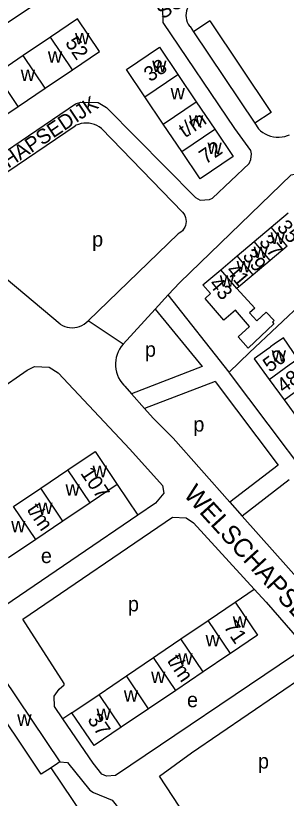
# Model space of a CAD drawing. Extents: x 157569 to 159501, y 382907 to 384670.
# Drawn here: x 157888.3 to 157961.3, y 383461.2 to 383672.3 of the extents above; entities that cross this region are included whole.
import ezdxf

# ---------------------------------------------------------------- set-up
doc = ezdxf.new("R2010")
doc.units = 0
for name, color, linetype in [('BLT_Basislijn', 7, 'Continuous'), ('BLT_Bebouwing', 7, 'Continuous'), ('BLT_Centroide', 7, 'Continuous'), ('BLT_Huisnummer', 7, 'Continuous'), ('BLT_Huisnummer_ tussenligend', 7, 'Continuous'), ('BLT_Huisnummer_reeks', 7, 'Continuous'), ('BLT_Onderverdeling_panden', 7, 'Continuous'), ('BLT_Straatnaam', 7, 'Continuous'), ('BLT_Straatnaam_verkleind', 7, 'Continuous'), ('BLT_Vlakafsluiter', 7, 'Continuous')]:
    doc.layers.add(name, color=color, linetype=linetype)

msp = doc.modelspace()

# ---------------------------------------------------------------- linework, layer by layer
at = {"layer": 'BLT_Basislijn'}
for p, q in [((157935.32, 383669.37), (157936.25, 383667.97)), ((157940.69, 383670.91), (157936.25, 383667.97)), ((157940.69, 383670.91), (157957.21, 383646.24)), ((157936.25, 383667.97), (157952.77, 383643.3)), ((157957.21, 383646.24), (157952.77, 383643.3)), ((157874.02, 383622.13), (157904.29, 383642.61)), ((157911.38, 383641.91), (157933.3, 383619.32)), ((157952.77, 383643.3), (157953.76, 383641.83)), ((157932.13, 383613.5), (157907.78, 383590)), ((157900.25, 383589.1), (157873.18, 383611.66)), ((157925.91, 383593.18), (157929.4, 383596.99)), ((157945.83, 383576.21), (157929.4, 383596.99)), ((157951.4, 383581.47), (157966.29, 383595.52)), ((157917.25, 383583.72), (157925.91, 383593.18)), ((157925.91, 383593.18), (157938.62, 383577.68)), ((157945.83, 383576.21), (157951.4, 383581.47)), ((157853.07, 383550.04), (157891.35, 383576.71)), ((157891.35, 383576.71), (157893.35, 383577.67)), ((157893.35, 383577.67), (157897.29, 383577.53)), ((157897.29, 383577.53), (157899.74, 383575.96)), ((157938.62, 383577.68), (157919.5, 383570.36)), ((157945.96, 383576.04), (157945.83, 383576.21)), ((157899.74, 383575.96), (157919.04, 383555.43)), ((157917.7, 383572.4), (157919.5, 383570.36)), ((157942.05, 383573.64), (157923.05, 383566.37)), ((157942.05, 383573.64), (157959.08, 383551.13)), ((157919.5, 383570.36), (157923.05, 383566.37)), ((157930.73, 383558.34), (157946.02, 383541.11)), ((157919.04, 383555.43), (157927.92, 383545.6)), ((157959.08, 383551.13), (157946.02, 383541.11)), ((157962.09, 383547.14), (157949.35, 383537.37)), ((157915.68, 383545.86), (157921.25, 383537.6)), ((157927.92, 383545.6), (157928.24, 383543.53)), ((157928.24, 383543.53), (157925.97, 383540.8)), ((157925.97, 383540.8), (157921.25, 383537.6)), ((157946.02, 383541.11), (157949.35, 383537.37)), ((157890.22, 383509.51), (157930.57, 383537.05)), ((157921.25, 383537.6), (157905.1, 383526.62)), ((157930.57, 383537.05), (157934.31, 383536.89)), ((157934.31, 383536.89), (157936.2, 383535.5)), ((157949.35, 383537.37), (157967.86, 383516.53)), ((157936.2, 383535.5), (157952.62, 383517.63)), ((157905.1, 383526.62), (157881.98, 383510.92)), ((157947.49, 383514.16), (157952.62, 383517.63)), ((157952.62, 383517.63), (157955.82, 383514.15)), ((157955.82, 383514.15), (157964.81, 383503.83)), ((157901.32, 383492.17), (157890.22, 383509.51)), ((157963.47, 383499.9), (157915.24, 383467.35)), ((157935.73, 383473.49), (157967.37, 383495.16)), ((157899.97, 383490.66), (157901.32, 383491.81)), ((157901.32, 383491.81), (157901.32, 383492.17)), ((157898.69, 383488.81), (157899.97, 383490.66)), ((157898.72, 383486.02), (157898.69, 383488.81)), ((157901, 383482.68), (157898.72, 383486.02)), ((157903.42, 383484.31), (157901, 383482.68)), ((157909.18, 383470.74), (157901, 383482.68)), ((157927.09, 383467.24), (157935.73, 383473.49)), ((157911.47, 383467.73), (157909.18, 383470.74)), ((157912.81, 383467.17), (157911.47, 383467.73)), ((157915.24, 383467.35), (157912.81, 383467.17)), ((157937.5, 383451.44), (157927.09, 383467.24))]:
    msp.add_line(p, q, dxfattribs=at)
for points in [[(157849.16, 383645.95), (157901.4, 383680.85), (157902.2, 383681.76), (157902.2, 383683.83), (157901.03, 383691.15), (157902.59, 383694.05), (157950.12, 383726.54), (157951.51, 383728.33), (157951.56, 383730.31), (157949.83, 383734.99), (157949.96, 383736.96), (157951.53, 383739.07), (157998.59, 383771.01), (158000.27, 383773.05), (157998.84, 383780.62), (157999.18, 383782.35), (158000.27, 383783.91), (158001.13, 383784.78), (158012.48, 383792.44), (158028.06, 383802.67), (158031.54, 383806.22)], [(157936, 383676.12), (157935.55, 383675.71), (157935.15, 383675.25), (157934.81, 383674.74), (157934.54, 383674.18), (157934.35, 383673.6), (157934.23, 383673), (157934.2, 383672.39), (157934.24, 383671.78), (157934.36, 383671.18), (157934.56, 383670.6), (157934.84, 383670.05), (157935.18, 383669.54), (157935.32, 383669.37)], [(157870.72, 383625.74), (157904.44, 383648.53), (157905.88, 383649.04), (157910.55, 383648.92), (157912.74, 383647.58), (157936.78, 383623.25), (157938.04, 383622.55), (157940.54, 383622.77), (157941.33, 383623.14), (157951.24, 383632.5), (157951.73, 383633.52), (157951.92, 383635.09), (157951.72, 383635.92), (157947.37, 383641.87), (157928.08, 383670.48), (157927.96, 383674.44)], [(157911.38, 383641.91), (157910.8, 383642.33), (157910.17, 383642.68), (157909.5, 383642.96), (157908.81, 383643.17), (157908.1, 383643.3), (157907.38, 383643.35), (157906.66, 383643.32), (157905.95, 383643.21), (157905.25, 383643.02), (157904.58, 383642.76), (157904.29, 383642.61)], [(157953.76, 383641.83), (157954.33, 383641.31), (157954.95, 383640.84), (157955.62, 383640.45), (157956.33, 383640.12), (157957.06, 383639.86), (157957.82, 383639.69), (157958.59, 383639.59), (157959.37, 383639.57), (157960.14, 383639.63), (157960.91, 383639.77), (157961.65, 383639.99), (157962.15, 383640.18)], [(157929.4, 383596.99), (157932.53, 383600.35), (157962.64, 383629.4), (157965.37, 383629.97), (157966.89, 383629.37), (157979.66, 383616.22)], [(157933.3, 383619.32), (157933.63, 383618.89), (157933.89, 383618.41), (157934.08, 383617.9), (157934.2, 383617.37), (157934.23, 383616.82), (157934.19, 383616.28), (157934.06, 383615.75), (157933.87, 383615.24), (157933.59, 383614.77), (157933.26, 383614.34), (157932.86, 383613.96), (157932.41, 383613.65), (157932.13, 383613.5)], [(157900.25, 383589.1), (157900.85, 383588.76), (157901.48, 383588.49), (157902.14, 383588.29), (157902.82, 383588.18), (157903.5, 383588.14), (157904.19, 383588.18), (157904.86, 383588.3), (157905.52, 383588.51), (157906.15, 383588.78), (157906.74, 383589.12), (157907.29, 383589.54), (157907.78, 383590)], [(157917.25, 383583.72), (157916.75, 383583.09), (157916.3, 383582.41), (157915.93, 383581.7), (157915.63, 383580.95), (157915.4, 383580.17), (157915.26, 383579.38), (157915.19, 383578.57), (157915.2, 383577.77), (157915.29, 383576.96), (157915.46, 383576.18), (157915.71, 383575.41), (157916.03, 383574.67), (157916.43, 383573.96), (157916.89, 383573.3), (157917.41, 383572.68), (157917.7, 383572.4)], [(157984.43, 383524.35), (157977.53, 383534.1), (157945.96, 383576.04)], [(157923.05, 383566.37), (157925.34, 383563.78), (157930.73, 383558.34)], [(157900.13, 383471.06), (157902.27, 383470.88), (157908.27, 383463.42), (157909.23, 383462.78), (157914.26, 383460.73), (157916.71, 383457.67), (157916.85, 383456.29), (157913.24, 383453.69)], [(157909.71, 383451.79), (157897.8, 383469.49)]]:
    msp.add_lwpolyline(points, dxfattribs=at)
at = {"layer": 'BLT_Bebouwing'}
for p, q in [((157897.64, 383666.51), (157890.32, 383661.56)), ((157890.32, 383661.56), (157883, 383656.62)), ((157896.25, 383652.77), (157903.58, 383657.71)), ((157932.03, 383656.44), (157937, 383649.08)), ((157888.93, 383647.83), (157896.25, 383652.77)), ((157928.09, 383643.06), (157923.12, 383650.42)), ((157937, 383649.08), (157941.98, 383641.72)), ((157881.61, 383642.89), (157888.93, 383647.83)), ((157933.07, 383635.7), (157928.09, 383643.06)), ((157957.18, 383615.28), (157961.75, 383619.14)), ((157952.6, 383611.42), (157957.18, 383615.28)), ((157948.03, 383607.56), (157952.6, 383611.42)), ((157961.49, 383610.16), (157956.92, 383606.3)), ((157943.58, 383603.8), (157948.03, 383607.56)), ((157956.92, 383606.3), (157952.34, 383602.45)), ((157952.34, 383602.45), (157947.94, 383598.74)), ((157952.63, 383579.76), (157956.67, 383574.23)), ((157956.67, 383574.23), (157960.71, 383568.7)), ((157960.71, 383568.7), (157964.75, 383563.17)), ((157895.02, 383544.86), (157902.36, 383549.81)), ((157887.69, 383539.92), (157895.02, 383544.86)), ((157908.35, 383540.92), (157901.02, 383535.97)), ((157901.02, 383535.97), (157893.69, 383531.02)), ((157893.69, 383531.02), (157886.36, 383526.08)), ((157932.81, 383504.21), (157940.16, 383509.19)), ((157918.12, 383494.25), (157925.48, 383499.21)), ((157910.77, 383489.28), (157918.12, 383494.25)), ((157938.83, 383495.31), (157931.47, 383490.34)), ((157931.47, 383490.34), (157924.12, 383485.38)), ((157924.12, 383485.38), (157916.76, 383480.41))]:
    msp.add_line(p, q, dxfattribs=at)
for points in [[(157903.58, 383657.71), (157910.89, 383662.65), (157904.96, 383671.44), (157897.64, 383666.51)], [(157923.12, 383650.42), (157918.15, 383657.78), (157927.05, 383663.8), (157932.03, 383656.44)], [(157941.98, 383641.72), (157946.95, 383634.36), (157938.04, 383628.34), (157933.07, 383635.7)], [(157957.93, 383589.23), (157950.99, 383582.65), (157948.28, 383585.74), (157951.38, 383588.46), (157947.54, 383592.91), (157944.42, 383590.21), (157939.35, 383596.08), (157940.83, 383597.36), (157938.76, 383599.74), (157943.58, 383603.8)], [(157947.94, 383598.74), (157952.77, 383593.42), (157951.39, 383592.15), (157953.38, 383590.01), (157955.87, 383592.35), (157957.99, 383590.11), (157957.52, 383589.67), (157957.93, 383589.23)], [(157962.07, 383578.17), (157964.39, 383579.8), (157960.49, 383585.42), (157958.02, 383583.7), (157957.05, 383582.99), (157956.89, 383582.87), (157956.46, 383582.56), (157952.63, 383579.76)], [(157902.36, 383549.81), (157909.68, 383554.75), (157915.68, 383545.86)], [(157915.68, 383545.86), (157908.35, 383540.92)], [(157940.16, 383509.19), (157947.49, 383514.16)], [(157947.49, 383514.16), (157953.53, 383505.25), (157946.19, 383500.27)], [(157925.48, 383499.21), (157926.6, 383500), (157932.81, 383504.21)], [(157946.19, 383500.27), (157945.77, 383500), (157938.83, 383495.31)], [(157879.89, 383490.47), (157884.86, 383493.81), (157900.13, 383471.06)], [(157897.8, 383469.49), (157895.16, 383467.72), (157879.89, 383490.47)], [(157903.42, 383484.31), (157910.77, 383489.28)], [(157916.76, 383480.41), (157909.41, 383475.44), (157903.42, 383484.31)], [(157900.13, 383471.06), (157899.51, 383470.64), (157897.8, 383469.49)]]:
    msp.add_lwpolyline(points, dxfattribs=at)
at = {"layer": 'BLT_Onderverdeling_panden'}
for p, q in [((157903.58, 383657.71), (157897.64, 383666.51)), ((157896.25, 383652.77), (157890.32, 383661.56)), ((157888.93, 383647.83), (157883, 383656.62)), ((157923.12, 383650.42), (157932.03, 383656.44)), ((157928.09, 383643.06), (157937, 383649.08)), ((157933.07, 383635.7), (157941.98, 383641.72)), ((157956.92, 383606.3), (157952.6, 383611.42)), ((157952.34, 383602.45), (157948.03, 383607.56)), ((157947.94, 383598.74), (157943.58, 383603.8)), ((157956.67, 383574.23), (157962.07, 383578.17)), ((157960.71, 383568.7), (157966.11, 383572.64)), ((157908.35, 383540.92), (157902.36, 383549.81)), ((157901.02, 383535.97), (157895.02, 383544.86)), ((157893.69, 383531.02), (157887.69, 383539.92)), ((157946.19, 383500.27), (157940.16, 383509.19)), ((157938.83, 383495.31), (157932.81, 383504.21)), ((157931.47, 383490.34), (157925.48, 383499.21)), ((157924.12, 383485.38), (157918.12, 383494.25)), ((157916.76, 383480.41), (157910.77, 383489.28))]:
    msp.add_line(p, q, dxfattribs=at)
msp.add_lwpolyline([(157961.49, 383610.16), (157957.18, 383615.28)], dxfattribs=at)
at = {"layer": 'BLT_Vlakafsluiter'}
msp.add_line((157917.25, 383583.72), (157907.78, 383590), dxfattribs=at)

# ---------------------------------------------------------------- texts
at = {"layer": 'BLT_Centroide'}
for s, p in [('w', (157904.27, 383664.58)), ('w', (157896.95, 383659.64)), ('w', (157925.09, 383657.12)), ('w', (157889.62, 383654.7)), ('w', (157930.06, 383649.75)), ('w', (157935.03, 383642.38)), ('w', (157940.01, 383635.03)), ('p', (157908.89, 383610.05)), ('w', (157957.05, 383610.78)), ('w', (157952.47, 383606.94)), ('w', (157947.89, 383603.06)), ('w', (157943.33, 383599.22)), ('p', (157923.14, 383580.34)), ('w', (157957.34, 383578.97)), ('p', (157936.21, 383560.14)), ('w', (157909.02, 383547.84)), ('w', (157901.69, 383542.89)), ('w', (157894.36, 383537.94)), ('w', (157887.03, 383533)), ('e', (157895.07, 383524.68)), ('p', (157918.55, 383511.66)), ('w', (157946.84, 383507.22)), ('w', (157939.5, 383502.25)), ('w', (157932.16, 383497.28)), ('w', (157924.8, 383492.3)), ('w', (157917.44, 383487.33)), ('e', (157934.49, 383485.82)), ('w', (157910.09, 383482.36)), ('w', (157888.68, 383480.77)), ('p', (157953.64, 383469.27))]:
    msp.add_text(s, height=4, dxfattribs=at).set_placement(p)
at = {"layer": 'BLT_Huisnummer'}
for s, rotation, p in [('37', 310.1478, (157953.75, 383611.19)), ('43', 310.1478, (157940.23, 383599.83)), ('50', 36.2313, (157956.83, 383575.95))]:
    msp.add_text(s, height=4, rotation=rotation, dxfattribs=at).set_placement(p)
at = {"layer": 'BLT_Huisnummer_ tussenligend'}
for s, rotation, p in [('35', 310.1478, (157958.53, 383615.17)), ('39', 310.1478, (157949.28, 383607.41)), ('41', 310.1478, (157944.81, 383603.42)), ('48', 36.2313, (157960.56, 383570.35))]:
    msp.add_text(s, height=4, rotation=rotation, dxfattribs=at).set_placement(p)
at = {"layer": 'BLT_Huisnummer_reeks'}
for s, rotation, p in [('52', 304.0121, (157901.47, 383665)), ('38', 34.0478, (157924.56, 383654.32)), ('t/m', 34.0478, (157933.96, 383639.25)), ('72', 34.0493, (157939.49, 383632.12)), ('107', 304.0076, (157905.6, 383548.92)), ('t/m', 304.0076, (157891.14, 383539.13)), ('71', 304.0337, (157944.25, 383507.48)), ('t/m', 304.0337, (157928.99, 383498.37)), ('37', 304.0337, (157907.47, 383482.46))]:
    msp.add_text(s, height=4, rotation=rotation, dxfattribs=at).set_placement(p)
at = {"layer": 'BLT_Straatnaam'}
msp.add_text('WELSCHAPSEDIJK', height=5, rotation=312.3482, dxfattribs=at).set_placement((157933.35, 383543.01))
at = {"layer": 'BLT_Straatnaam_verkleind'}
for s, p in [('SCHELTEMAWEG', (157927.99, 383671.23)), ('WELSCHAPSEDIJK', (157870.47, 383620.46))]:
    msp.add_text(s, height=4, rotation=33.8624, dxfattribs=at).set_placement(p)

doc.saveas('drawing.dxf')
